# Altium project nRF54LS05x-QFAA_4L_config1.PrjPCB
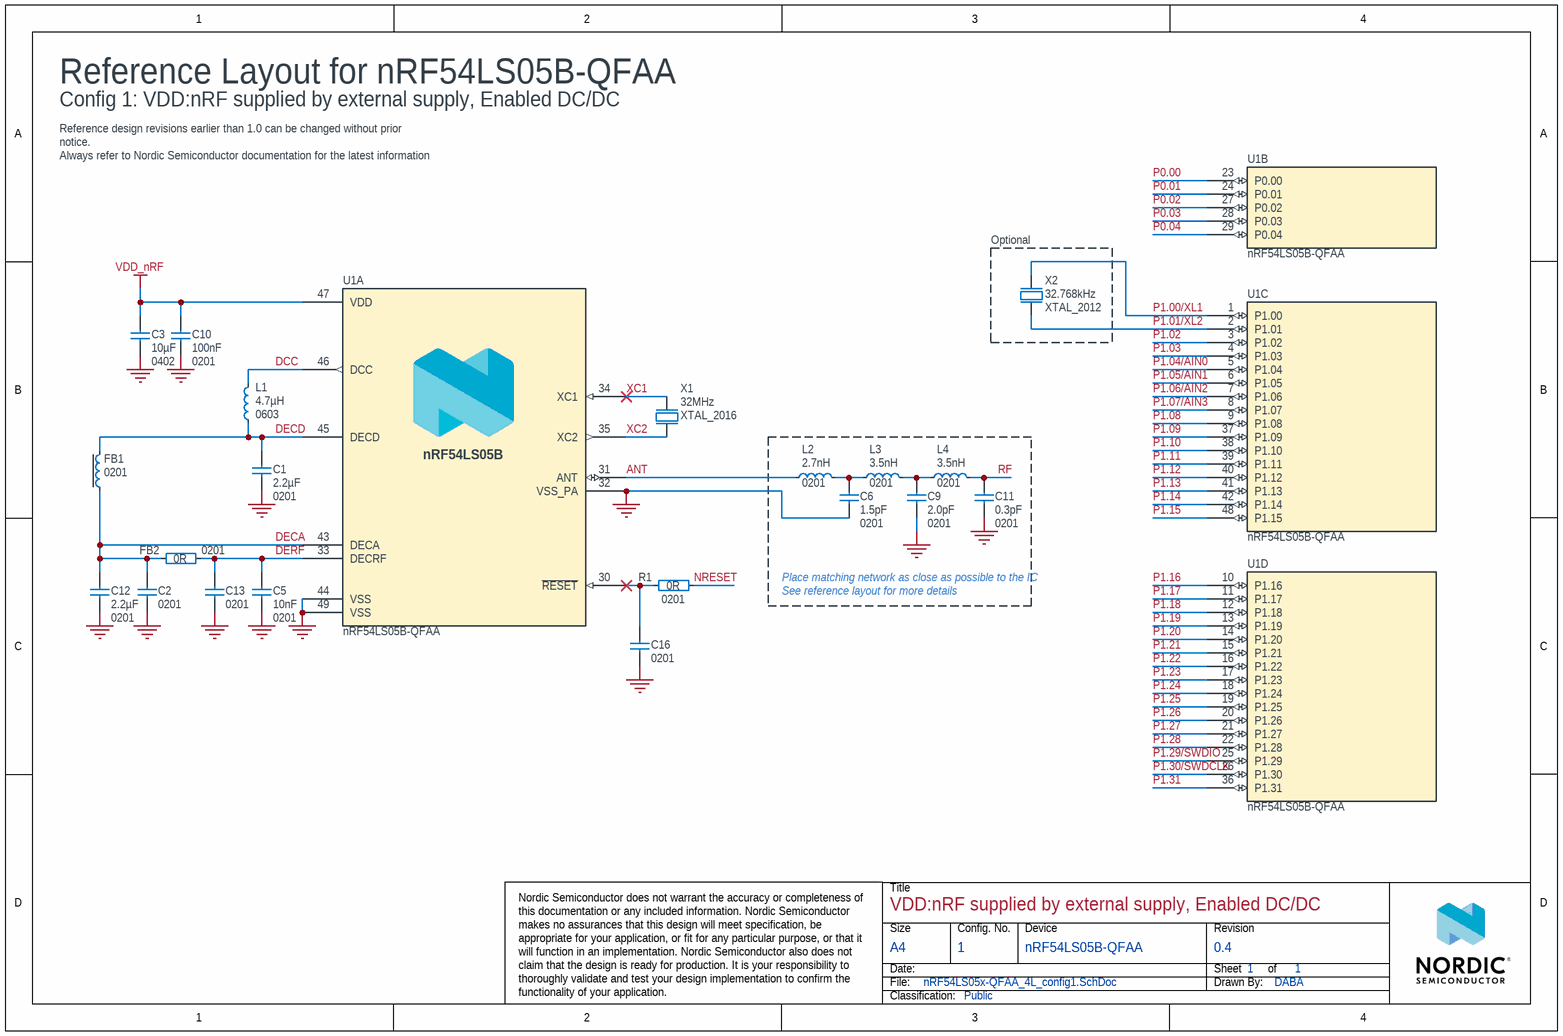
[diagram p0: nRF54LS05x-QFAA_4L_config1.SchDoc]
Revision: 0.4; RefLayoutTitle: VDD:nRF supplied by external supply, Enabled DC/DC; DrawnBy: DABA; Device: nRF54LS05B-QFAA; Config: 1; Classification: Public
1 sheet, 21 parts. Net scope: global (net labels, ports and power ports of the same name join across sheets).
Board file: nRF54LS05x-QFAA_4L_config1.PcbDoc

## Sheet nRF54LS05x-QFAA_4L_config1.SchDoc
size A4; Organization: Nordic Semiconductor; SheetNumber: 1; SheetTotal: 1; DocumentSize: A4

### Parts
C1  2.2µF  Footprint Doc: 0201  [CAPC0603X03L_C]
C2  Footprint Doc: 0201  [CAPC0603X03L_C]  (hidden comment: 2.2µF)
C3  10µF  Footprint Doc: 0402  [CAPC1005X04L]
C5  Footprint Doc: 0201  [CAPC0603X03L_C]  (hidden comment: 10nF)
C6  1.5pF  Footprint Doc: 0201  [CAPC0603X03L_C]
C9  2.0pF  Footprint Doc: 0201  [CAPC0603X03L_C]
C10  100nF  Footprint Doc: 0201  [CAPC0603X03L_C]
C11  0.3pF  Footprint Doc: 0201  [CAPC0603X03L_C]
C12  Footprint Doc: 0201  [CAPC0603X03L_C]  (hidden comment: 2.2µF)
C13  Footprint Doc: 0201  [CAPC0603X03L_C]  (hidden comment: 2.2µF)
C16  Footprint Doc: 0201  [CAPC0603X03L_C]  (hidden comment: 3.9pF)
FB1  Footprint Doc: 0201  [INDC0603X03L_C]  (hidden comment: 120R/0.2A)
FB2  Footprint Doc: 0201  [RESC0603X03L_C]  (hidden comment: 0R)
L1  4.7µH  Footprint Doc: 0603  [INDC1608X06L]
L2  2.7nH  Footprint Doc: 0201  [INDC0603X03L_C]
L3  3.5nH  Footprint Doc: 0201  [INDC0603X03L_C]
L4  3.5nH  Footprint Doc: 0201  [INDC0603X03L_C]
R1  0R  Footprint Doc: 0201  [RESC0603X03L_C]
U1  nRF54LS05B-QFAA  [QFN49P40_600x600x90L40x20T460N]  (parts A,B,C,D of 4)
X1  32MHz  Footprint Doc: XTAL_2016  [BT-XTAL_2016]
X2  32.768kHz  [XTAL_2012]

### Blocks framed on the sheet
Optional: X2

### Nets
GND: C1.1 C2.1 C3.1 C5.1 C6.1 C9.1 C10.1 C11.1 C12.2 C13.2 C16.2 U1.32(VSS_PA) U1.44(VSS) U1.49(VSS) X1.2(GND) X1.4(GND)
VDD_nRF: C3.2 C10.2 U1.47(VDD)
ANT: L2.1 U1.31(ANT)
DCC: L1.1 U1.46(DCC)
DECA: C2.2 C12.1 FB1.2 FB2.2 U1.43(DECA)
DECD: C1.2 FB1.1 L1.2 U1.45(DECD)
DERF: C5.2 C13.1 FB2.1 U1.33(DECRF)
NRESET: R1.2
P0.00: U1.23(P0.00)
P0.01: U1.24(P0.01)
P0.02: U1.27(P0.02)
P0.03: U1.28(P0.03)
P0.04: U1.29(P0.04)
P1.00/XL1: U1.1(P1.00) X2.2(out)
P1.01/XL2: U1.2(P1.01) X2.1(inp)
P1.02: U1.3(P1.02)
P1.03: U1.4(P1.03)
P1.04/AIN0: U1.5(P1.04)
P1.05/AIN1: U1.6(P1.05)
P1.06/AIN2: U1.7(P1.06)
P1.07/AIN3: U1.8(P1.07)
P1.08: U1.9(P1.08)
P1.09: U1.37(P1.09)
P1.10: U1.38(P1.10)
P1.11: U1.39(P1.11)
P1.12: U1.40(P1.12)
P1.13: U1.41(P1.13)
P1.14: U1.42(P1.14)
P1.15: U1.48(P1.15)
P1.16: U1.10(P1.16)
P1.17: U1.11(P1.17)
P1.18: U1.12(P1.18)
P1.19: U1.13(P1.19)
P1.20: U1.14(P1.20)
P1.21: U1.15(P1.21)
P1.22: U1.16(P1.22)
P1.23: U1.17(P1.23)
P1.24: U1.18(P1.24)
P1.25: U1.19(P1.25)
P1.26: U1.20(P1.26)
P1.27: U1.21(P1.27)
P1.28: U1.22(P1.28)
P1.29/SWDIO: U1.25(P1.29)
P1.30/SWDCLK: U1.26(P1.30)
P1.31: U1.36(P1.31)
RF: C11.2 L4.2
XC1: U1.34(XC1) X1.1(inp)
XC2: U1.35(XC2) X1.3(out)
NetC6_2: C6.2 L2.2 L3.1
NetC9_2: C9.2 L3.2 L4.1
NetC16_1: C16.1 R1.1 U1.30(~{RESET})

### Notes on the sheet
- Place matching network as close as possible to the IC
- See reference layout for more details

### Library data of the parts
C1 C2 C12 C13 = C0201-2µ2-2.5V-X6T-GRM033D80E225ME47D: Capacitor, Ceramic, 2.2µF 2.5V X6T 0201,±20%; Manufacturer: Murata; Part number NEMS: 100200527; Component Status: Active; Pad Count: 2; Note: 2.5V, 20%, X6T; Artikkelnr Noca: N.A.
C3 = C0402-10µF-6.3V-X6S: Capacitor, X6S, ±20%, 6.3V; Manufacturer: N.A.; Part number NEMS: 100200478; Component Status: Active; Pad Count: 2
C5 = C0201-10n-6.3V-X7R: Capacitor, X7R, 6.3V; Manufacturer: Murata; Manufacturer Part Number: GRM033R70J103KA01D; Part number NEMS: 100200407; Component Status: Active; Pad Count: 2; Artikkelnr Noca: N.A.
C6 = C0201-1.5p-25V-NP0-GJM0335C1E1R5WB01: Capacitor, NP0, ±0.05pF, 25V, High Q; Manufacturer: Murata; Part number NEMS: 100200477; Component Status: Active; Pad Count: 2; Artikkelnr Noca: N.A.
C9 = C0201-2.0p-HQ-Murata: Capacitor, NP0, ±0.05pF, 25V; Manufacturer: Murata; Manufacturer Part Number: GJM0335C1E2R0WB01; Part number IPS: 00000001775; Part number NEMS: 100200419; Component Status: Active; Pad Count: 2; Artikkelnr Noca: N.A.
C10 = C0201-100n-10V-X7R: Capacitor, X7R, ±10%, 10V; Manufacturer: N.A.; Part number NEMS: 100200469; Pad Count: 2; Component Status: Active
C11 = C0201-0.3p-50V-GRM0335C1HR30BA01: Capacitor, C0G, ±0.1pF, 50V; Manufacturer: Murata; Part number NEMS: 100200650; Component Status: Active; Pad Count: 2; Artikkelnr Noca: N.A.
C16 = C0201-3.9p: Chip Cap 0201; Manufacturer: N.A.; Part number NEMS: 100200024,100200424; Component Status: Active; Pad Count: 2; Note: Chip Cap 1%
FB1 = FB0201-120R@100M-200mA-BLM03AG121SN1D: Ferrite Bead, 120 Ohm @ 100MHz, 200mA, 500 mOhm Max; Manufacturer: Murata; Part number NEMS: 100300419; Component Status: Active; Pad Count: 2; Artikkelnr Noca: N.A.
FB2 R1 = R0201-0R-5%-0.05W-RC0201JR-070RL: 0 Ohms Jumper 0.05W, 1/20W Chip Resistor 0201 (0603 Metric) Moisture Resistant Thick Film; Manufacturer: Yageo; Part number NEMS: 100100652; Component Status: Active; Pad Count: 2; Note: Chip Res 5%; Artikkelnr Noca: N.A.
L1 = L0603-4µ7-MLZ1608M4R7WT000: Inductor, 120mA, ±20%, 0.65R; Manufacturer: TDK Corporation; Part number NEMS: 100300440; Component Status: Active; Pad Count: 2; Note: Power Inductor ±20%; Artikkelnr Noca: N.A.
L2 = L0201-2n7-HQ-Murata: Inductor, 600mA, ±0.1ｎH, 120mOhm; Manufacturer: Murata; Manufacturer Part Number: LQP03HQ2N7B02; Part number IPS: 00000001753; Part number NEMS: 100300214; Component Status: Active; Pad Count: 2; Note: -55°C ~ 125°C; Artikkelnr Noca: N.A.
L3 L4 = L0201-3n5-HQ-Murata: Inductor, 500mA, ±0.1ｎH, 170mOhm; Manufacturer: Murata; Manufacturer Part Number: LQP03HQ3N5B02; Part number NEMS: 100300222; Component Status: Active; Pad Count: 2; Note: -55°C ~ 125°C; Artikkelnr Noca: N.A.
U1 = nRF54LS05B-QFAA: Ultra-low-power Bluetooth LE SoC with 508 KB NVM and 96 KB  RAM, supporting Bluetooth LE and 2.4 GHz proprietary protocols; Manufacturer: Nordic Semiconductor; Part number NEMS: 102000422; Component Status: Active; Pad Count: 49; Note: N.A.
X1 = XTAL_SMD2016_32MHz_8pF_Kyocera: XTAL SMD 2016, 32MHz, Cl=8pF, Tot: ±40ppm; Manufacturer Part Number: CX2016DB32000D0WZRC1; Part number IPS: 00000007827; Part number Norautron: 26511136; Part number NEMS: 101600039; Component Status: Active; Pad Count: 4; Note: XTAL SMD 32.000MHz; Artikkelnr Noca: 22010022
X2 = XTAL_SMD2012_32.768kHz_9pF_TXC: XTAL SMD 2012, 32.768kHz, 9pF, ±20ppm; Manufacturer: TXC Corporation; Manufacturer Part Number: 9HT11-32.768KDZC-T; Part number NEMS: 101600107; Component Status: Active; Pad Count: 2; Note: XTAL SMD 32.768kHz; Artikkelnr Noca: N.A.

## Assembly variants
default: not fitted C2 C13 C16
